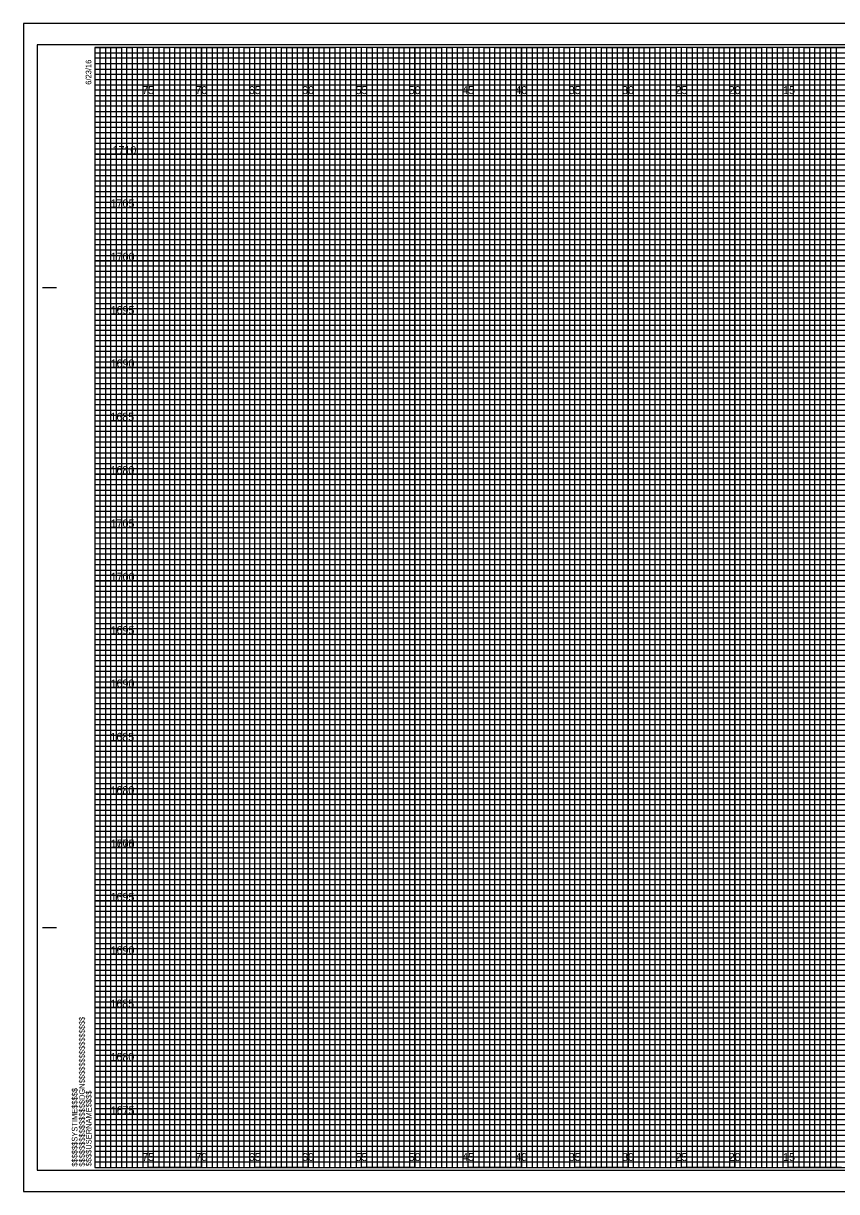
# Model space of a CAD drawing. Extents: x -7 to 162, y -2 to 217.
# Drawn here: x -6.7 to 69.5, y 107.7 to 217.2 of the extents above; entities that cross this region are included whole.
import ezdxf

# ---------------------------------------------------------------- set-up
doc = ezdxf.new("R2010")
doc.units = 0
for name, color, linetype in [('Raster_Level_0', 7, 'Continuous'), ('Scratch_Level_3', 7, 'Continuous'), ('Sheet Cross Section CELL', 7, 'Continuous'), ('Sheet Cross Section Grid Major CELL', 7, 'Continuous'), ('Sheet Cross Section Grid Middle CELL', 7, 'Continuous'), ('Sheet Cross Section Grid Minor 1 CELL', 7, 'Continuous'), ('Sheet Cross Section Grid Minor 2 CELL', 7, 'Continuous'), ('Sheet Cutting Line CELL', 7, 'Continuous'), ('Sheet DOT Grid CELL', 7, 'Continuous'), ('Sheet Plot Border Inside CELL', 7, 'Continuous'), ('Sheet Plot Border Outside CELL', 7, 'Continuous')]:
    doc.layers.add(name, color=color, linetype=linetype)

msp = doc.modelspace()

# ---------------------------------------------------------------- linework, layer by layer
at = {"layer": 'Sheet Cross Section CELL'}
for p, q in [((-4.9, 192.5), (-3.65, 192.5)), ((-4.85, 192.5), (-3.6, 192.5)), ((-4.9, 132.5), (-3.65, 132.5)), ((-4.85, 132.5), (-3.6, 132.5)), ((0, 110), (0, 110)), ((0, 110), (0, 110)), ((0, 110), (0, 110)), ((0, 110), (0, 110)), ((0, 110), (0, 110)), ((0, 110), (0, 110)), ((0, 110), (0, 110))]:
    msp.add_line(p, q, dxfattribs=at)
msp.add_lwpolyline([(160, 215), (0, 215), (0, 110), (160, 110)], close=True, dxfattribs=at)
at = {"layer": 'Sheet Cross Section Grid Major CELL'}
for p, q in [((5, 215), (0, 215)), ((5, 110), (5, 215)), ((15, 215), (10, 215)), ((10, 215), (10, 110)), ((15, 110), (15, 215)), ((25, 215), (20, 215)), ((20, 215), (20, 110)), ((25, 110), (25, 215)), ((35, 215), (30, 215)), ((30, 215), (30, 110)), ((35, 110), (35, 215)), ((45, 215), (40, 215)), ((40, 215), (40, 110)), ((45, 110), (45, 215)), ((55, 215), (50, 215)), ((50, 215), (50, 110)), ((55, 110), (55, 215)), ((65, 215), (60, 215)), ((60, 215), (60, 110)), ((65, 110), (65, 215)), ((10, 110), (5, 110)), ((20, 110), (15, 110)), ((30, 110), (25, 110)), ((40, 110), (35, 110)), ((50, 110), (45, 110)), ((60, 110), (55, 110)), ((70, 110), (65, 110))]:
    msp.add_line(p, q, dxfattribs=at)
for points in [[(0, 210), (160, 210), (160, 205), (0, 205)], [(0, 200), (160, 200), (160, 195), (0, 195)], [(0, 190), (160, 190), (160, 185), (0, 185)], [(0, 180), (160, 180), (160, 175), (0, 175)], [(0, 170), (160, 170), (160, 165), (0, 165)], [(0, 160), (160, 160), (160, 155), (0, 155)], [(0, 150), (160, 150), (160, 145), (0, 145)], [(0, 140), (160, 140), (160, 135), (0, 135)], [(0, 130), (160, 130), (160, 125), (0, 125)], [(0, 120), (160, 120), (160, 115), (0, 115)]]:
    msp.add_lwpolyline(points, dxfattribs=at)
at = {"layer": 'Sheet Cross Section Grid Middle CELL'}
for points in [[(0, 215), (2.5, 215), (2.5, 110), (7.5, 110), (7.5, 215), (12.5, 215), (12.5, 110), (17.5, 110), (17.5, 215), (22.5, 215), (22.5, 110), (27.5, 110), (27.5, 215), (32.5, 215), (32.5, 110), (37.5, 110), (37.5, 215), (42.5, 215), (42.5, 110), (47.5, 110), (47.5, 215), (52.5, 215), (52.5, 110), (57.5, 110), (57.5, 215), (62.5, 215), (62.5, 110), (67.5, 110), (67.5, 215), (72.5, 215)], [(0, 212.5), (137.5, 212.5)], [(0, 202.5), (160, 202.5), (160, 207.5), (0, 207.5)], [(0, 192.5), (160, 192.5), (160, 197.5), (0, 197.5)], [(0, 182.5), (160, 182.5), (160, 187.5), (0, 187.5)], [(0, 172.5), (160, 172.5), (160, 177.5), (0, 177.5)], [(0, 162.5), (160, 162.5), (160, 167.5), (0, 167.5)], [(0, 152.5), (160, 152.5), (160, 157.5), (0, 157.5)], [(0, 142.5), (160, 142.5), (160, 147.5), (0, 147.5)], [(0, 132.5), (160, 132.5), (160, 137.5), (0, 137.5)], [(0, 122.5), (160, 122.5), (160, 127.5), (0, 127.5)], [(0, 112.5), (160, 112.5), (160, 117.5), (0, 117.5)]]:
    msp.add_lwpolyline(points, dxfattribs=at)
at = {"layer": 'Sheet Cross Section Grid Minor 1 CELL'}
for p, q in [((0, 214.5), (130, 214.5)), ((130, 213.99), (0, 213.99)), ((0, 213.99), (0, 213.5)), ((0, 213.5), (130, 213.5)), ((130, 212.94), (0, 212.94)), ((0, 212.94), (0, 212)), ((0, 212), (160, 212))]:
    msp.add_line(p, q, dxfattribs=at)
for points in [[(0, 211.5), (135, 211.5), (160, 211.5), (160, 211), (0, 211)], [(0, 210.5), (160, 210.5), (160, 209.5), (0, 209.5)], [(0, 209), (160, 209), (160, 208.5), (0, 208.49)], [(0, 208), (160, 208), (160, 207), (0, 207)], [(0, 206.5), (160, 206.5), (160, 206), (0, 206)], [(0, 205.5), (160, 205.5), (160, 204.5), (0, 204.5)], [(0, 204), (160, 204), (160, 203.5), (0, 203.5)], [(0, 203), (160, 203), (160, 202), (0, 202)], [(0, 201.5), (160, 201.5), (160, 201), (0, 201)], [(0, 200.5), (160, 200.5), (160, 199.5), (0, 199.5)], [(0, 199), (160, 199), (160, 198.5), (0, 198.5)], [(0, 198), (160, 198), (160, 196.97), (160, 196.5), (160, 196), (0, 196)], [(0, 197), (160, 197), (160, 196.5), (0, 196.5)], [(0, 195.5), (160, 195.5), (160, 194.5), (0, 194.52)], [(0, 194.52), (160, 194.5), (160, 194), (0, 194)], [(0, 193.5), (160, 193.5), (160, 193), (0, 193)], [(0, 192), (160, 192), (160, 191.5), (0, 191.5)], [(0, 191), (160, 191), (160, 190.5), (0, 190.5)], [(-0.04, 189.44), (160, 189.44), (160, 188.94), (-0.04, 188.94)], [(0, 188.5), (160, 188.5), (160, 188), (0, 188)], [(0, 187), (160, 187), (160, 186.5), (0, 186.5)], [(0, 186), (160, 186), (160, 185.5), (0, 185.5)], [(0, 184.5), (160, 184.5), (160, 184), (0, 184)], [(0, 183.5), (160, 183.5), (160, 183), (0, 183)], [(0, 182), (160, 182), (160, 181.5), (0, 181.5)], [(0, 181), (160, 181), (160, 180.5), (0, 180.5)], [(0, 179.5), (160, 179.5), (160, 178.99), (0, 179)], [(0, 178.5), (160, 178.5), (160, 178), (0, 178)], [(0, 177), (160, 177), (160, 176.5), (0, 176.5)], [(0, 176), (160, 176), (160, 175.5), (0, 175.5)], [(0, 174.5), (160, 174.5), (160, 174), (0, 174)], [(0, 173.5), (160, 173.5), (160, 173), (0, 173)], [(0, 172), (160, 172), (160, 171.5), (0, 171.5)], [(0, 171), (160, 171), (160, 170.5), (0, 170.5)], [(0, 169.5), (160, 169.5), (160, 169), (0, 169)], [(0, 168.5), (160.03, 168.46), (160, 168), (0, 168)], [(0, 167), (160, 167), (160, 166.5), (0, 166.5)], [(0, 166), (160, 166), (160, 165.5), (0, 165.5)], [(0, 164.5), (160, 164.5), (160, 164), (0, 164)], [(0, 163.5), (160, 163.5), (160, 163), (0, 163)], [(0, 162), (160, 162), (160, 161.5), (0, 161.5)], [(0, 161), (160, 161), (160, 160.5), (0, 160.5)], [(0, 159.5), (160, 159.5), (160, 159), (0, 159)], [(0, 158.5), (160, 158.5), (160, 158), (0, 158)], [(0, 157), (160, 157), (160, 156.5), (0, 156.5)], [(0, 156), (160, 156), (160, 155.5), (0, 155.5)], [(0, 154.5), (160, 154.5), (160, 154), (0, 154)], [(0, 153.5), (160, 153.5), (160, 153), (0, 153)], [(0, 152), (160, 152), (160, 151.5), (0, 151.5)], [(0, 151), (160, 151), (160, 150.5), (0, 150.5)], [(0, 149.5), (160, 149.5), (160, 148.99), (0, 149)], [(0, 148.5), (160, 148.5), (160, 148), (0, 148)], [(0, 147), (160, 147), (160, 146.5), (0, 146.5)], [(0, 146), (160, 146), (160, 145.5), (0, 145.5)], [(0, 144.5), (160, 144.5), (160, 144), (0, 144)], [(0, 143.5), (160, 143.5), (160, 143), (0, 143)], [(0, 142), (160, 142), (160, 141.5), (0, 141.5)], [(0, 141), (160, 141), (160, 140.5), (0, 140.5)], [(0, 139.5), (160, 139.5), (160, 139), (0, 139)], [(0, 138.5), (160.03, 138.46), (160, 138), (0, 138)], [(0, 137), (160, 137), (160, 136.5), (0, 136.5)], [(0, 136), (160, 136), (160, 135.5), (0, 135.5)], [(0, 134.5), (160, 134.5), (160, 134), (0, 134)], [(0, 133.5), (160, 133.5), (160, 133), (0, 133)], [(0, 132), (160, 132), (160, 131.5), (0, 131.5)], [(0, 131), (160, 131), (160, 130.5), (0, 130.5)], [(0, 129.5), (160, 129.5), (160, 129), (0, 129)], [(0, 128.5), (160, 128.5), (160, 128), (0, 128)], [(0, 127), (160, 127), (160, 126.5), (0, 126.5)], [(0, 126), (160, 126), (160, 125.5), (0, 125.5)], [(0, 124.5), (160, 124.5), (160, 124), (0, 124)], [(0, 123.5), (160, 123.5), (160, 123), (0, 123)], [(0, 122), (160, 122), (160, 121.5), (0, 121.5)], [(0, 121), (160, 121), (160, 120.5), (0, 120.5)], [(0, 119.5), (160, 119.5), (160, 119), (0, 119)], [(0, 118.5), (160, 118.5), (160, 118), (0, 118)], [(0, 117), (160, 117), (160, 116.5), (0, 116.5)], [(0, 116), (160, 116), (160, 115.5), (0, 115.5)], [(0, 114.5), (160, 114.5), (160, 114), (0, 114)], [(0, 113.5), (160, 113.5), (160, 113), (0, 113)], [(0, 112), (160, 112), (160, 111.5), (0, 111.5)], [(0, 111), (160, 111), (160, 110.5), (0, 110.5)]]:
    msp.add_lwpolyline(points, dxfattribs=at)
at = {"layer": 'Sheet Cross Section Grid Minor 2 CELL'}
for points in [[(0, 110), (0.5, 110), (0.5, 215), (1, 215), (1, 110)], [(1, 110), (1.5, 110), (1.5, 215), (2, 215), (2, 110)], [(2.5, 110), (3, 110), (3, 215), (3.5, 215), (3.5, 110)], [(3.5, 110), (4, 110), (4, 215), (4.5, 215), (4.5, 110)], [(5, 110), (5.5, 110), (5.5, 215), (6, 215), (6, 110)], [(6, 110), (6.5, 110), (6.5, 215), (7, 215), (7, 110)], [(7.5, 110), (8, 110), (8, 215), (8.5, 215), (8.5, 110)], [(8.5, 110), (9, 110), (9, 215), (9.5, 215), (9.5, 110)], [(10, 110), (10.5, 110), (10.5, 215), (11, 215), (11, 110)], [(11, 110), (11.5, 110), (11.5, 215), (12, 215), (12, 110)], [(12.5, 110), (13, 110), (13, 215), (13.5, 215), (13.5, 110)], [(13.5, 110), (14, 110), (14, 215), (14.5, 215), (14.5, 110)], [(15, 110), (15.5, 110), (15.5, 215), (16, 215), (16, 110)], [(16, 110), (16.5, 110), (16.5, 215), (17, 215), (17, 110)], [(17.5, 110), (18, 110), (18, 215), (18.5, 215), (18.5, 110)], [(18.5, 110), (19, 110), (19, 215), (19.5, 215), (19.5, 110)], [(20, 110), (20.5, 110), (20.5, 215), (21, 215), (21, 110)], [(21, 110), (21.5, 110), (21.5, 215), (22, 215), (22, 110)], [(22.5, 110), (23, 110), (23, 215), (23.5, 215), (23.5, 110)], [(23.5, 110), (24, 110), (24, 215), (24.5, 215), (24.5, 110)], [(25, 110), (25.5, 110), (25.5, 215), (26, 215), (26, 110)], [(26, 110), (26.5, 110), (26.5, 215), (27, 215), (27, 110)], [(27.5, 110), (28, 110), (28, 215), (28.5, 215), (28.5, 110)], [(28.5, 110), (29, 110), (29, 215), (29.5, 215), (29.5, 110)], [(30, 110), (30.5, 110), (30.5, 215), (31, 215), (31, 110)], [(31, 110), (31.5, 110), (31.5, 215), (32, 215), (32, 110)], [(32.5, 110), (33, 110), (33, 215), (33.5, 215), (33.5, 110)], [(33.5, 110), (34, 110), (34, 215), (34.5, 215), (34.5, 110)], [(35, 110), (35.5, 110), (35.5, 215), (36, 215), (36, 110)], [(36, 110), (36.5, 110), (36.5, 215), (37, 215), (37, 110)], [(37.5, 110), (38, 110), (38, 215), (38.5, 215), (38.5, 110)], [(38.5, 110), (39, 110), (39, 215), (39.5, 215), (39.5, 110)], [(40, 110), (40.5, 110), (40.5, 215), (41, 215), (41, 110)], [(41, 110), (41.5, 110), (41.5, 215), (42, 215), (42, 110)], [(42.5, 110), (43, 110), (43, 215), (43.5, 215), (43.5, 110)], [(43.5, 110), (44, 110), (44, 215), (44.5, 215), (44.5, 110)], [(45, 110), (45.5, 110), (45.5, 215), (46, 215), (46, 110)], [(46, 110), (46.5, 110), (46.5, 215), (47, 215), (47, 110)], [(47.5, 110), (48, 110), (48, 215), (48.5, 215), (48.5, 110)], [(48.5, 110), (49, 110), (49, 215), (49.5, 215), (49.5, 110)], [(50, 110), (50.5, 110), (50.5, 215), (51, 215), (51, 110)], [(51, 110), (51.5, 110), (51.5, 215), (52, 215), (52, 110)], [(52.5, 110), (53, 110), (53, 215), (53.5, 215), (53.5, 110)], [(53.5, 110), (54, 110), (54, 215), (54.5, 215), (54.5, 110)], [(55, 110), (55.5, 110), (55.5, 215), (56, 215), (56, 110)], [(56, 110), (56.5, 110), (56.5, 215), (57, 215), (57, 110)], [(57.5, 110), (58, 110), (58, 215), (58.5, 215), (58.5, 110)], [(58.5, 110), (59, 110), (59, 215), (59.5, 215), (59.5, 110)], [(60, 110), (60.5, 110), (60.5, 215), (61, 215), (61, 110)], [(61, 110), (61.5, 110), (61.5, 215), (62, 215), (62, 110)], [(62.5, 110), (63, 110), (63, 215), (63.5, 215), (63.5, 110)], [(63.5, 110), (64, 110), (64, 215), (64.5, 215), (64.5, 110)], [(65, 110), (65.5, 110), (65.5, 215), (66, 215), (66, 110)], [(66, 110), (66.5, 110), (66.5, 215), (67, 215), (67, 110)], [(67.5, 110), (68, 110), (68, 215), (68.5, 215), (68.5, 110)], [(68.5, 110), (69, 110), (69, 215), (69.5, 215), (69.5, 110)]]:
    msp.add_lwpolyline(points, dxfattribs=at)
at = {"layer": 'Sheet Cutting Line CELL'}
for p, q in [((161.65, 217.25), (-6.7, 217.25)), ((-6.7, 217.25), (-6.7, 107.75)), ((-6.7, 107.75), (161.65, 107.75))]:
    msp.add_line(p, q, dxfattribs=at)
at = {"layer": 'Sheet DOT Grid CELL'}
for p, q in [((5, 110), (5, 215)), ((10, 110), (10, 215)), ((15, 110), (15, 215)), ((20, 110), (20, 215)), ((25, 110), (25, 215)), ((30, 110), (30, 215)), ((35, 110), (35, 215)), ((40, 110), (40, 215)), ((45, 110), (45, 215)), ((50, 110), (50, 215)), ((55, 110), (55, 215)), ((60, 110), (60, 215)), ((65, 110), (65, 215)), ((0, 210), (160, 210)), ((0, 205), (160, 205)), ((0, 200), (160, 200)), ((0, 195), (160, 195)), ((0, 190), (160, 190)), ((0, 185), (160, 185)), ((0, 180), (160, 180)), ((0, 175), (160, 175)), ((0, 170), (160, 170)), ((0, 165), (160, 165)), ((0, 160), (160, 160)), ((0, 155), (160, 155)), ((0, 150), (160, 150)), ((0, 145), (160, 145)), ((0, 140), (160, 140)), ((0, 135), (160, 135)), ((0, 130), (160, 130)), ((0, 125), (160, 125)), ((0, 120), (160, 120)), ((0, 115), (160, 115))]:
    msp.add_line(p, q, dxfattribs=at)
at = {"layer": 'Sheet Plot Border Inside CELL'}
msp.add_lwpolyline([(-5.4, 109.75), (161.2, 109.75), (161.2, 215.25), (-5.4, 215.25)], close=True, dxfattribs=at)
at = {"layer": 'Sheet Plot Border Outside CELL'}
msp.add_lwpolyline([(-6.7, 107.75), (161.65, 107.75), (161.65, 217.25), (-6.7, 217.25)], close=True, dxfattribs=at)

# ---------------------------------------------------------------- texts
at = {"layer": 'Raster_Level_0'}
for s, p in [('75', (4.44, 210.62)), ('70', (9.43, 210.62)), ('65', (14.44, 210.62)), ('60', (19.43, 210.62)), ('55', (24.44, 210.62)), ('50', (29.43, 210.62)), ('45', (34.44, 210.62)), ('40', (39.43, 210.62)), ('35', (44.44, 210.62)), ('30', (49.43, 210.62)), ('25', (54.44, 210.62)), ('20', (59.43, 210.62)), ('15', (64.53, 210.62)), ('75', (4.44, 110.62)), ('70', (9.43, 110.62)), ('65', (14.44, 110.62)), ('60', (19.43, 110.62)), ('55', (24.44, 110.62)), ('50', (29.43, 110.62)), ('45', (34.44, 110.62)), ('40', (39.43, 110.62)), ('35', (44.44, 110.62)), ('30', (49.43, 110.62)), ('25', (54.44, 110.62)), ('20', (59.43, 110.62)), ('15', (64.53, 110.62))]:
    msp.add_text(s, height=0.75, dxfattribs=at).set_placement(p)
at = {"layer": 'Scratch_Level_3'}
for s, p in [('1710', (1.66, 205)), ('1705', (1.48, 200)), ('1700', (1.49, 195)), ('1695', (1.48, 190)), ('1690', (1.48, 185)), ('1685', (1.46, 180)), ('1680', (1.47, 175)), ('1705', (1.48, 170)), ('1700', (1.49, 165)), ('1695', (1.48, 160)), ('1690', (1.48, 155)), ('1685', (1.46, 150)), ('1680', (1.47, 145)), ('1700', (1.49, 140)), ('1675', (1.49, 140)), ('1695', (1.48, 135)), ('1690', (1.48, 130)), ('1685', (1.46, 125)), ('1680', (1.47, 120)), ('1675', (1.49, 115))]:
    msp.add_text(s, height=0.75, dxfattribs=at).set_placement(p)
at = {"layer": 'Sheet Cross Section CELL'}
for s, p in [('6/23/16', (-0.33, 211.5)), ('$$$$$$$$$$$$$$$$DGN$$$$$$$$$$$$$$$$', (-0.94, 110.09)), ('$$$$$$SYSTIME$$$$$', (-1.63, 110.09)), ('$$$$USERNAME$$$$', (-0.31, 110.12))]:
    msp.add_text(s, height=0.525, rotation=90, dxfattribs=at).set_placement(p)

doc.saveas('drawing.dxf')
